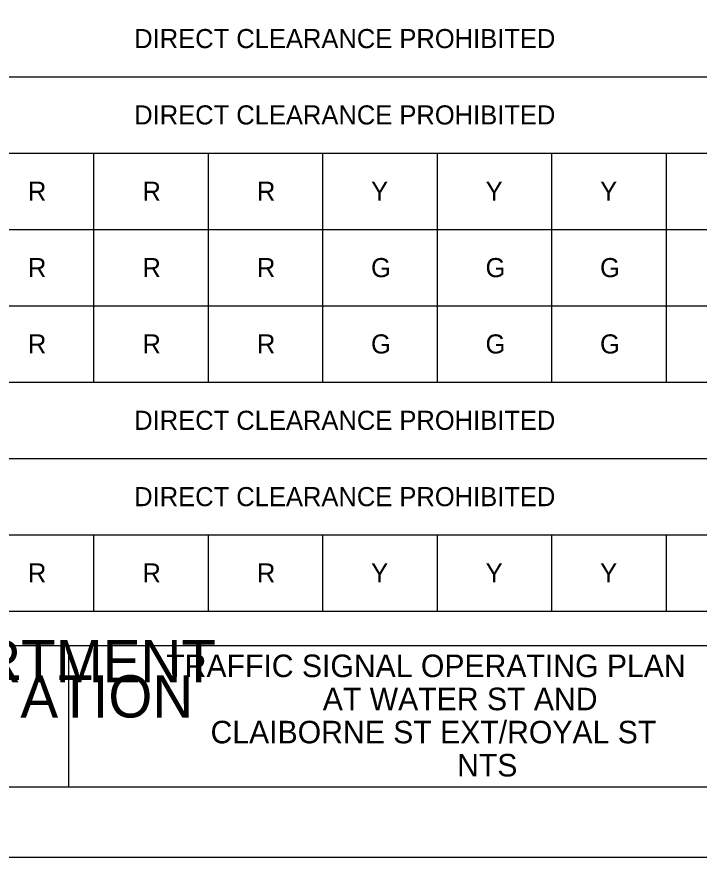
# Model space of a CAD drawing. Extents: x 515543 to 517243, y 660510 to 662861.
# Drawn here: x 516666.4 to 516908.5, y 660510.2 to 660808.4 of the extents above; entities that cross this region are included whole.
import ezdxf

# ---------------------------------------------------------------- set-up
doc = ezdxf.new("R2010")
doc.units = 0
for name, color, linetype in [('ANNO-TXT', 7, 'Continuous'), ('C-TOPO-TEXT', 7, 'Continuous'), ('Default', 7, 'Continuous'), ('Level 62', 7, 'Continuous'), ('SHT-BDR', 7, 'Continuous'), ('SHT-BNDRY', 7, 'Continuous')]:
    doc.layers.add(name, color=color, linetype=linetype)

msp = doc.modelspace()

# ---------------------------------------------------------------- linework, layer by layer
at = {"layer": 'Default'}
for p, q in [((516520.97, 660787.13), (517018.66, 660787.13)), ((516520.97, 660787.13), (517018.66, 660787.13)), ((516693.66, 660787.13), (517018.66, 660787.13)), ((516693.66, 660787.13), (517018.66, 660787.13)), ((516520.97, 660760.04), (517008.47, 660760.04)), ((516520.97, 660760.04), (517018.66, 660760.04)), ((516693.66, 660760.04), (516693.66, 660678.79)), ((516734.28, 660760.04), (516734.28, 660678.79)), ((516774.91, 660760.04), (516774.91, 660678.79)), ((516815.53, 660760.04), (516815.53, 660678.79)), ((516856.16, 660760.04), (516856.16, 660678.79)), ((516896.78, 660760.04), (516896.78, 660678.79)), ((516439.72, 660732.96), (517130.34, 660732.96)), ((516520.97, 660705.88), (517008.47, 660705.88)), ((516520.97, 660705.88), (517018.66, 660705.88)), ((516520.97, 660678.79), (517018.66, 660678.79)), ((516520.97, 660678.79), (517018.66, 660678.79)), ((516693.66, 660678.79), (517018.66, 660678.79)), ((516693.66, 660678.79), (517018.66, 660678.79)), ((516520.97, 660651.71), (517008.47, 660651.71)), ((516520.97, 660651.71), (517018.66, 660651.71)), ((516520.97, 660624.63), (517018.66, 660624.63)), ((516520.97, 660624.63), (517008.47, 660624.63)), ((516520.97, 660624.63), (517008.47, 660624.63)), ((516693.66, 660624.63), (516693.66, 660597.54)), ((516734.28, 660624.63), (516734.28, 660597.54)), ((516774.91, 660624.63), (516774.91, 660597.54)), ((516815.53, 660624.63), (516815.53, 660597.54)), ((516856.16, 660624.63), (516856.16, 660597.54)), ((516896.78, 660624.63), (516896.78, 660597.54)), ((516439.72, 660597.54), (517130.34, 660597.54))]:
    msp.add_line(p, q, dxfattribs=at)
at = {"layer": 'Level 62'}
msp.add_lwpolyline([(515542.51, 660510.25), (517242.52, 660510.25), (517242.52, 661610.25), (515542.51, 661610.25)], close=True, dxfattribs=at)
at = {"layer": 'SHT-BDR'}
msp.add_lwpolyline([(515667.5, 660585.3), (517167.5, 660585.3), (517167.5, 661535.3), (515667.5, 661535.3)], close=True, dxfattribs=at)
at = {"layer": 'SHT-BNDRY'}
msp.add_line((516684.86, 660535.25), (516684.86, 660585.3), dxfattribs=at)
msp.add_lwpolyline([(515605.01, 660535.25), (517217.52, 660535.25), (517217.52, 661585.25), (515605.01, 661585.25)], close=True, dxfattribs=at)

# ---------------------------------------------------------------- texts
at = {"layer": 'ANNO-TXT'}
for s, p in [('ALABAMA DEPARTMENT', (516498.51, 660572.3)), ('OF TRANSPORTATION', (516510.56, 660559.8))]:
    msp.add_text(s, height=15, rotation=360, dxfattribs=at).set_placement(p)
at = {"layer": 'C-TOPO-TEXT'}
for s, p in [('TRAFFIC SIGNAL OPERATING PLAN', (516719.43, 660574.13)), ('AT WATER ST AND', (516774.96, 660562.38)), ('CLAIBORNE ST EXT/ROYAL ST', (516735.14, 660550.63)), ('NTS', (516822.61, 660538.88))]:
    msp.add_text(s, height=8, rotation=0.0003, dxfattribs=at).set_placement(p)
at = {"layer": 'Default'}
for s, height, p in [('DIRECT CLEARANCE PROHIBITED', 6.7708, (516708.06, 660797.28)), ('DIRECT CLEARANCE PROHIBITED', 6.7708, (516708.06, 660770.2)), ('R', 6.77, (516670.36, 660743.12)), ('R', 6.77, (516710.99, 660743.12)), ('R', 6.77, (516751.61, 660743.12)), ('Y', 6.77, (516792.11, 660743.12)), ('Y', 6.77, (516832.74, 660743.12)), ('Y', 6.77, (516873.36, 660743.12)), ('R', 6.77, (516670.36, 660716.03)), ('R', 6.77, (516710.99, 660716.03)), ('R', 6.77, (516751.61, 660716.03)), ('G', 6.77, (516792.09, 660716.03)), ('G', 6.77, (516832.71, 660716.03)), ('G', 6.77, (516873.34, 660716.03)), ('R', 6.77, (516670.36, 660688.95)), ('R', 6.77, (516710.99, 660688.95)), ('R', 6.77, (516751.61, 660688.95)), ('G', 6.77, (516792.09, 660688.95)), ('G', 6.77, (516832.71, 660688.95)), ('G', 6.77, (516873.34, 660688.95)), ('DIRECT CLEARANCE PROHIBITED', 6.7708, (516708.06, 660661.86)), ('DIRECT CLEARANCE PROHIBITED', 6.7708, (516708.06, 660634.78)), ('R', 6.77, (516670.36, 660607.7)), ('R', 6.77, (516710.99, 660607.7)), ('R', 6.77, (516751.61, 660607.7)), ('Y', 6.77, (516792.11, 660607.7)), ('Y', 6.77, (516832.74, 660607.7)), ('Y', 6.77, (516873.36, 660607.7))]:
    msp.add_text(s, height=height, dxfattribs=at).set_placement(p)

doc.saveas('drawing.dxf')
